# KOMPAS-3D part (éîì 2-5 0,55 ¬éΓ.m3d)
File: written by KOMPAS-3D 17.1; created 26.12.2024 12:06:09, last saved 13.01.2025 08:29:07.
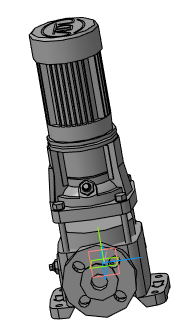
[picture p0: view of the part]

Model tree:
1. Операция без истории:3  (labels: ВМН 2-5 0,55 кВт)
